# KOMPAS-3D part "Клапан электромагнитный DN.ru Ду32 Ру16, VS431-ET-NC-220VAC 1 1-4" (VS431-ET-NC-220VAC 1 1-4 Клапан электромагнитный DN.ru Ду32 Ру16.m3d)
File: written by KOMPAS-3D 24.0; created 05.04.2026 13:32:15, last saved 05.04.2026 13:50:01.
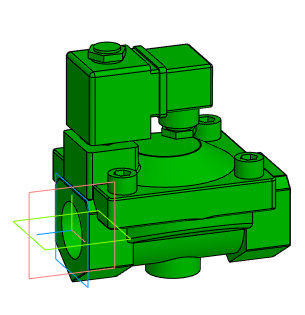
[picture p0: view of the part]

Document properties: Автор: artio; Полное имя файла: C:\Users\artio\OneDrive\Рабочий стол\Клапан электромагнитный DN.ru\VS431\VS431-ET-NC\VS431-ET-NC-220VAC\Ду32\VS431-ET-NC-220VAC 1 1-4 Клапан электромагнитный DN.ru Ду32 Ру16.m3d

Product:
- Body: Тело 1  | qty 1
    Масса: 3.709873
- Part/product: Клапан электромагнитный DN.ru Ду32 Ру16  | designation VS431-ET-NC-220VAC 1 1-4
    Масса: 1.701
    Раздел спецификации: Прочие изделия
    Примечание: D130-04708
    additional columns: ef56311e-7521-43dc-8291-0e6108b3d81d; artio; c; Шероховатость не задана; Да

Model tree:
1. Операция без истории:1

Expressions: VS431-ET-NC-220VAC 1 1-4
